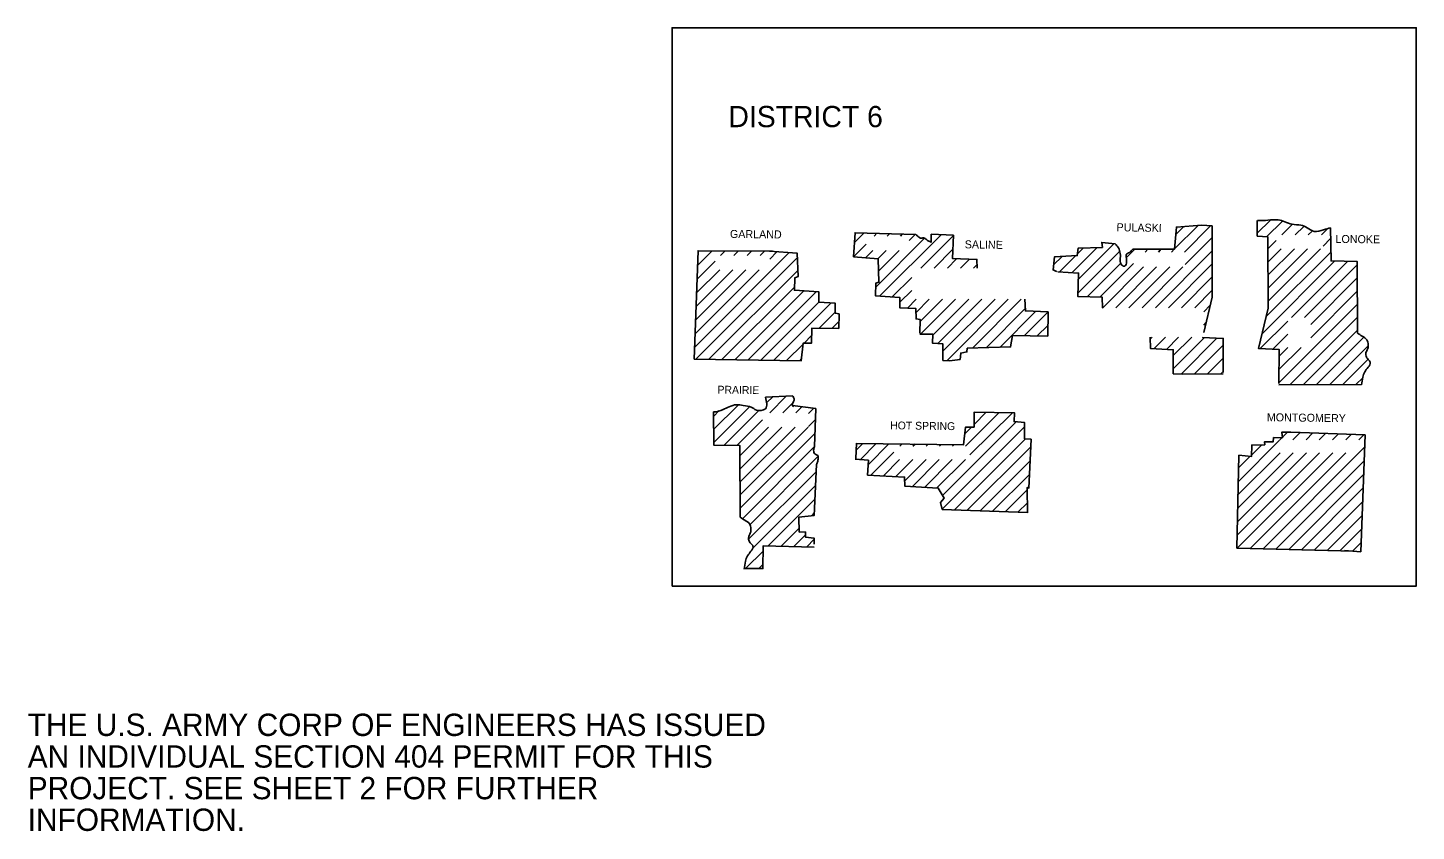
# Model space of a CAD drawing. Extents: x 21307 to 29830, y 1322443 to 1332359.
# Drawn here: x 27242 to 27988, y 1326076 to 1326507 of the extents above; entities that cross this region are included whole.
import ezdxf

# ---------------------------------------------------------------- set-up
doc = ezdxf.new("R2010")
doc.units = 0
doc.layers.add('R_Draft', color=7, linetype='Continuous')

msp = doc.modelspace()

# ---------------------------------------------------------------- linework, layer by layer
at = {"layer": 'R_Draft'}
for p, q in [((27727.22, 1326392.26), (27727.22, 1326396.66)), ((27693.42, 1326275.06), (27686.32, 1326275.76))]:
    msp.add_line(p, q, dxfattribs=at)
msp.add_lwpolyline([(27587.92, 1326207.46), (27587.92, 1326507.46), (27987.92, 1326507.46), (27987.92, 1326207.46)], close=True, dxfattribs=at)
for points in [[(27685.42, 1326384.46), (27686.32, 1326397.36), (27719.02, 1326396.36)], [(27835.52, 1326388.46), (27858.02, 1326388.56), (27859.02, 1326400.36), (27872.42, 1326401.36)], [(27858.02, 1326388.66), (27870.62, 1326401.26)], [(27858.72, 1326396.36), (27863.02, 1326400.66)], [(27863.42, 1326386.96), (27877.42, 1326400.96)], [(27872.42, 1326401.36), (27878.22, 1326400.96), (27878.32, 1326362.76), (27873.72, 1326343.66)], [(27902.42, 1326397.06), (27909.52, 1326404.06)], [(27902.42, 1326395.46), (27902.42, 1326403.86)], [(27907.52, 1326395.06), (27916.02, 1326403.56)], [(27915.72, 1326396.16), (27921.42, 1326401.86)], [(27922.82, 1326396.16), (27927.42, 1326400.76)], [(27929.92, 1326396.16), (27932.02, 1326398.26)], [(27936.92, 1326396.16), (27940.02, 1326399.26)], [(27941.92, 1326400.06), (27942.12, 1326382.16), (27956.22, 1326381.86), (27956.32, 1326343.46)], [(27685.42, 1326384.46), (27692.22, 1326391.26)], [(27685.92, 1326392.06), (27691.12, 1326397.26)], [(27696.52, 1326395.56), (27698.02, 1326397.06)], [(27697.42, 1326368.16), (27723.42, 1326394.26)], [(27699.62, 1326363.36), (27732.52, 1326396.26)], [(27703.62, 1326395.56), (27704.72, 1326396.76)], [(27710.72, 1326395.56), (27711.62, 1326396.56)], [(27715.32, 1326393.16), (27718.52, 1326396.36)], [(27721.72, 1326378.36), (27739.02, 1326395.66)], [(27727.22, 1326396.66), (27739.12, 1326395.96), (27738.72, 1326383.46), (27751.82, 1326382.96), (27751.92, 1326378.36)], [(27727.22, 1326392.26), (27727.22, 1326392.16)], [(27794.52, 1326376.36), (27794.52, 1326376.46), (27792.72, 1326377.36), (27793.42, 1326384.36), (27805.72, 1326385.06), (27806.12, 1326388.96), (27819.22, 1326389.46), (27818.92, 1326392.16), (27826.12, 1326391.36)], [(27806.32, 1326372.36), (27825.32, 1326391.36)], [(27863.72, 1326380.26), (27878.22, 1326394.76)], [(27914.12, 1326316.26), (27914.22, 1326334.66), (27903.12, 1326335.16), (27908.32, 1326356.86), (27908.22, 1326395.06), (27902.42, 1326395.46)], [(27908.22, 1326388.66), (27912.72, 1326393.16)], [(27937.92, 1326390.16), (27941.92, 1326394.16)], [(27599.72, 1326329.36), (27601.92, 1326387.66), (27641.92, 1326387.46)], [(27600.02, 1326335.76), (27650.92, 1326386.66)], [(27600.72, 1326329.36), (27655.22, 1326383.86)], [(27601.62, 1326379.76), (27609.42, 1326387.56)], [(27601.92, 1326387.06), (27602.42, 1326387.66)], [(27614.02, 1326385.06), (27616.52, 1326387.56)], [(27621.12, 1326385.06), (27623.52, 1326387.46)], [(27628.22, 1326385.06), (27630.62, 1326387.46)], [(27635.22, 1326385.06), (27637.62, 1326387.46)], [(27640.32, 1326387.46), (27655.22, 1326386.36), (27655.62, 1326373.76), (27653.92, 1326373.16), (27653.72, 1326366.46), (27666.82, 1326365.56), (27666.82, 1326360.06), (27675.52, 1326359.56), (27675.62, 1326354.06), (27677.72, 1326353.76), (27677.62, 1326345.86)], [(27640.42, 1326383.16), (27644.32, 1326387.06)], [(27721.12, 1326343.36), (27721.22, 1326350.76), (27719.12, 1326351.06), (27719.02, 1326356.56), (27710.32, 1326357.06), (27710.32, 1326362.56), (27697.22, 1326363.46), (27697.42, 1326370.16), (27699.12, 1326370.76), (27698.72, 1326383.36), (27685.42, 1326384.36)], [(27691.92, 1326383.86), (27695.92, 1326387.86)], [(27698.52, 1326383.36), (27703.02, 1326387.86)], [(27699.02, 1326376.86), (27710.02, 1326387.86)], [(27728.72, 1326378.36), (27738.82, 1326388.46)], [(27735.92, 1326378.36), (27740.82, 1326383.36)], [(27742.92, 1326378.36), (27747.72, 1326383.16)], [(27793.02, 1326380.16), (27797.52, 1326384.66)], [(27796.22, 1326376.36), (27805.02, 1326385.16)], [(27802.92, 1326375.96), (27816.22, 1326389.26)], [(27805.82, 1326385.96), (27808.92, 1326389.06)], [(27806.02, 1326364.96), (27828.52, 1326387.36)], [(27832.02, 1326383.86), (27836.62, 1326388.46)], [(27842.22, 1326386.96), (27843.72, 1326388.46)], [(27847.72, 1326357.06), (27878.22, 1326387.66)], [(27849.32, 1326386.96), (27850.72, 1326388.46)], [(27856.32, 1326386.96), (27857.82, 1326388.46)], [(27907.32, 1326352.36), (27942.12, 1326387.16)], [(27908.32, 1326360.56), (27936.42, 1326388.66)], [(27908.32, 1326367.56), (27929.42, 1326388.66)], [(27908.32, 1326374.66), (27922.42, 1326388.66)], [(27908.32, 1326381.66), (27915.32, 1326388.66)], [(27600.32, 1326343.06), (27634.72, 1326377.46)], [(27600.52, 1326350.36), (27627.62, 1326377.46)], [(27600.82, 1326357.76), (27620.62, 1326377.46)], [(27601.12, 1326365.06), (27613.52, 1326377.46)], [(27601.42, 1326372.46), (27611.02, 1326382.06)], [(27607.72, 1326329.36), (27655.52, 1326377.06)], [(27750.02, 1326378.36), (27751.82, 1326380.16)], [(27819.32, 1326357.06), (27819.12, 1326362.66), (27806.02, 1326363.16), (27806.42, 1326375.66), (27795.22, 1326376.36)], [(27811.12, 1326362.96), (27829.22, 1326381.06)], [(27817.92, 1326362.66), (27836.02, 1326380.76)], [(27819.32, 1326356.96), (27819.42, 1326357.06), (27841.32, 1326378.96)], [(27826.42, 1326357.06), (27848.32, 1326378.96)], [(27833.52, 1326357.06), (27855.42, 1326378.96)], [(27840.62, 1326357.06), (27862.52, 1326378.96)], [(27854.72, 1326357.06), (27878.22, 1326380.56)], [(27905.02, 1326343.06), (27944.02, 1326382.06)], [(27920.92, 1326351.86), (27950.92, 1326381.86)], [(27927.92, 1326351.86), (27956.22, 1326380.16)], [(27614.72, 1326329.16), (27653.72, 1326368.16)], [(27706.22, 1326362.86), (27716.72, 1326373.36)], [(27861.82, 1326357.06), (27878.22, 1326373.56)], [(27931.22, 1326348.06), (27956.22, 1326373.06)], [(27621.72, 1326329.06), (27658.72, 1326366.16)], [(27628.62, 1326328.96), (27665.32, 1326365.66)], [(27635.62, 1326328.86), (27666.82, 1326360.06)], [(27710.32, 1326359.96), (27716.72, 1326366.36)], [(27714.42, 1326356.86), (27719.12, 1326361.56)], [(27719.12, 1326354.56), (27726.12, 1326361.56)], [(27721.22, 1326349.56), (27733.22, 1326361.56)], [(27721.52, 1326342.76), (27740.32, 1326361.56)], [(27728.12, 1326342.36), (27747.42, 1326361.56)], [(27730.72, 1326337.86), (27754.42, 1326361.56)], [(27733.52, 1326333.66), (27761.52, 1326361.56)], [(27735.62, 1326328.56), (27768.62, 1326361.56)], [(27749.42, 1326335.36), (27775.62, 1326361.56)], [(27777.52, 1326361.56), (27777.82, 1326355.36), (27790.02, 1326354.76), (27789.92, 1326341.76)], [(27868.92, 1326357.06), (27878.22, 1326366.46)], [(27931.22, 1326340.96), (27956.22, 1326365.96)], [(27642.62, 1326328.86), (27673.42, 1326359.66)], [(27666.82, 1326345.96), (27675.52, 1326354.66)], [(27756.72, 1326335.56), (27777.72, 1326356.56)], [(27764.02, 1326335.76), (27783.22, 1326355.06)], [(27777.22, 1326341.86), (27790.02, 1326354.76)], [(27873.72, 1326354.86), (27877.22, 1326358.36)], [(27914.22, 1326316.86), (27956.22, 1326358.86)], [(27677.62, 1326345.86), (27663.02, 1326346.06), (27662.92, 1326338.06), (27658.42, 1326338.06), (27657.32, 1326328.56), (27599.72, 1326329.36)], [(27673.82, 1326345.86), (27677.62, 1326349.66)], [(27784.22, 1326341.86), (27789.92, 1326347.56)], [(27873.72, 1326347.76), (27875.02, 1326349.06)], [(27904.22, 1326335.26), (27918.82, 1326349.86)], [(27920.02, 1326315.66), (27956.22, 1326351.86)], [(27658.92, 1326338.06), (27662.92, 1326342.06)], [(27737.12, 1326328.46), (27733.52, 1326328.76), (27733.52, 1326337.56), (27727.92, 1326337.96), (27728.12, 1326342.76), (27721.12, 1326342.86)], [(27789.92, 1326341.76), (27770.82, 1326342.06), (27769.92, 1326335.96), (27746.62, 1326335.26), (27746.42, 1326333.26), (27743.12, 1326332.66), (27742.72, 1326329.26), (27737.12, 1326328.46)], [(27857.22, 1326321.46), (27857.32, 1326334.46), (27845.12, 1326335.06), (27844.82, 1326341.26)], [(27844.92, 1326340.16), (27846.02, 1326341.26)], [(27846.82, 1326334.96), (27853.12, 1326341.26)], [(27853.62, 1326334.66), (27860.22, 1326341.26)], [(27857.22, 1326324.26), (27874.02, 1326340.96)], [(27857.32, 1326331.36), (27867.22, 1326341.26)], [(27861.52, 1326321.36), (27880.82, 1326340.76)], [(27873.22, 1326341.26), (27873.12, 1326341.06), (27884.22, 1326340.56), (27884.12, 1326322.16)], [(27911.02, 1326334.96), (27918.82, 1326342.76)], [(27927.12, 1326315.66), (27956.22, 1326344.76)], [(27934.22, 1326315.66), (27959.62, 1326341.06)], [(27649.52, 1326328.66), (27658.32, 1326337.46)], [(27868.62, 1326321.36), (27884.12, 1326336.96)], [(27914.22, 1326323.96), (27926.02, 1326335.76)], [(27914.22, 1326331.06), (27918.92, 1326335.76)], [(27941.32, 1326315.66), (27961.92, 1326336.36)], [(27656.52, 1326328.56), (27657.42, 1326329.56)], [(27875.72, 1326321.46), (27884.12, 1326329.86)], [(27882.82, 1326321.46), (27884.12, 1326322.86)], [(27948.42, 1326315.76), (27962.12, 1326329.46)], [(27862.02, 1326321.36), (27857.22, 1326321.46)], [(27884.12, 1326321.56), (27862.02, 1326321.36)], [(27958.52, 1326315.76), (27914.12, 1326315.56)], [(27955.52, 1326315.76), (27959.22, 1326319.46)], [(27638.12, 1326308.96), (27652.62, 1326309.66)], [(27639.12, 1326306.36), (27641.82, 1326309.06)], [(27640.42, 1326300.56), (27649.32, 1326309.46)], [(27610.12, 1326298.56), (27613.32, 1326301.76)], [(27624.52, 1326244.56), (27624.42, 1326282.96), (27610.32, 1326283.26), (27610.12, 1326301.16)], [(27610.22, 1326291.56), (27623.42, 1326304.76)], [(27610.32, 1326284.66), (27629.52, 1326303.86)], [(27615.92, 1326283.16), (27634.52, 1326301.76)], [(27647.42, 1326300.56), (27653.12, 1326306.26)], [(27652.62, 1326304.46), (27665.12, 1326302.86), (27664.42, 1326282.46)], [(27654.52, 1326300.56), (27657.72, 1326303.76)], [(27661.22, 1326300.26), (27664.02, 1326302.96)], [(27687.02, 1326284.06), (27744.62, 1326283.46), (27745.72, 1326292.96), (27750.22, 1326292.96), (27750.32, 1326300.96), (27771.92, 1326300.66), (27771.72, 1326295.86), (27777.32, 1326295.46), (27777.32, 1326286.66), (27780.92, 1326286.36), (27779.72, 1326260.16), (27778.82, 1326260.46), (27778.92, 1326246.86)], [(27745.72, 1326282.66), (27763.82, 1326300.76)], [(27748.02, 1326277.96), (27770.82, 1326300.66)], [(27750.22, 1326294.26), (27756.82, 1326300.86)], [(27622.72, 1326282.96), (27636.62, 1326296.86)], [(27624.42, 1326277.56), (27639.82, 1326292.96)], [(27624.52, 1326256.46), (27661.02, 1326292.96)], [(27624.52, 1326263.56), (27654.02, 1326292.96)], [(27624.52, 1326270.56), (27646.92, 1326292.96)], [(27661.22, 1326293.16), (27664.92, 1326296.86)], [(27733.12, 1326248.86), (27777.32, 1326293.06)], [(27733.32, 1326256.16), (27772.82, 1326295.66)], [(27745.32, 1326289.26), (27748.92, 1326292.96)], [(27624.52, 1326249.36), (27664.62, 1326289.46)], [(27739.82, 1326248.46), (27777.92, 1326286.66)], [(27891.5, 1326227.87), (27892.6, 1326277.77), (27899.4, 1326277.17), (27899.5, 1326283.27), (27906.5, 1326283.47), (27906.4, 1326285.07), (27911.1, 1326285.07), (27911.2, 1326287.27), (27916, 1326287.17), (27915.6, 1326290.17), (27920.6, 1326290.27)], [(27892.3, 1326263.77), (27914.4, 1326285.87)], [(27914.6, 1326286.07), (27915.7, 1326287.17)], [(27915.9, 1326287.37), (27918.7, 1326290.17)], [(27920.6, 1326290.27), (27960.4, 1326288.77)], [(27921.6, 1326286.07), (27925.6, 1326290.07)], [(27928.7, 1326286.07), (27932.4, 1326289.77)], [(27935.8, 1326286.07), (27939.3, 1326289.57)], [(27942.9, 1326286.07), (27946.1, 1326289.27)], [(27950, 1326286.07), (27952.9, 1326288.97)], [(27957, 1326286.07), (27959.7, 1326288.77)], [(27960.4, 1326288.77), (27958.1, 1326225.97)], [(27626.02, 1326243.76), (27664.02, 1326281.86)], [(27686.72, 1326275.96), (27687.02, 1326284.26)], [(27686.92, 1326280.46), (27690.52, 1326284.06)], [(27689.12, 1326275.56), (27697.52, 1326283.96)], [(27693.42, 1326272.76), (27704.52, 1326283.96)], [(27694.82, 1326267.06), (27707.12, 1326279.46)], [(27710.42, 1326282.66), (27711.52, 1326283.86)], [(27717.42, 1326282.66), (27718.52, 1326283.76)], [(27724.52, 1326282.66), (27725.42, 1326283.56)], [(27731.62, 1326282.66), (27732.42, 1326283.46)], [(27738.72, 1326282.66), (27739.42, 1326283.46)], [(27746.62, 1326248.26), (27780.72, 1326282.26)], [(27891.6, 1326227.77), (27891.7, 1326227.87), (27943.1, 1326279.17)], [(27891.7, 1326234.87), (27936, 1326279.17)], [(27891.8, 1326242.07), (27928.9, 1326279.17)], [(27892, 1326249.37), (27921.8, 1326279.17)], [(27892.1, 1326256.57), (27914.7, 1326279.17)], [(27898.6, 1326227.67), (27950.1, 1326279.17)], [(27899.5, 1326278.07), (27904.9, 1326283.37)], [(27905.6, 1326227.57), (27960.2, 1326282.17)], [(27906.4, 1326284.97), (27906.6, 1326285.07)], [(27629.92, 1326240.56), (27666.32, 1326277.06)], [(27665.52, 1326272.86), (27664.32, 1326245.46), (27656.12, 1326244.56), (27656.32, 1326236.46), (27659.62, 1326236.56), (27659.72, 1326233.76), (27664.22, 1326233.26), (27664.32, 1326229.96)], [(27778.92, 1326247.06), (27733.12, 1326248.66), (27732.22, 1326252.36), (27734.12, 1326254.76), (27731.02, 1326260.16), (27713.02, 1326261.26), (27712.92, 1326266.06), (27693.02, 1326267.16), (27693.42, 1326275.06)], [(27701.52, 1326266.76), (27710.22, 1326275.46)], [(27708.22, 1326266.36), (27717.32, 1326275.46)], [(27713.02, 1326264.06), (27724.42, 1326275.46)], [(27717.12, 1326261.06), (27731.52, 1326275.46)], [(27723.72, 1326260.66), (27738.52, 1326275.46)], [(27730.32, 1326260.26), (27745.62, 1326275.46)], [(27753.52, 1326247.96), (27780.32, 1326274.86)], [(27892.4, 1326270.97), (27898.7, 1326277.27)], [(27912.4, 1326227.37), (27959.9, 1326274.77)], [(27629.02, 1326232.66), (27665.32, 1326268.96)], [(27760.22, 1326247.66), (27780.02, 1326267.46)], [(27919.4, 1326227.17), (27959.6, 1326267.47)], [(27631.52, 1326228.06), (27665.02, 1326261.56)], [(27767.02, 1326247.46), (27778.82, 1326259.16)], [(27926.2, 1326226.97), (27959.3, 1326260.07)], [(27639.62, 1326229.16), (27664.72, 1326254.16)], [(27773.82, 1326247.16), (27778.92, 1326252.16)], [(27933.1, 1326226.87), (27959.1, 1326252.77)], [(27662.82, 1326245.26), (27664.32, 1326246.76)], [(27940.1, 1326226.67), (27958.8, 1326245.47)], [(27646.52, 1326228.96), (27656.32, 1326238.66)], [(27653.42, 1326228.76), (27659.72, 1326235.06)], [(27946.9, 1326226.47), (27958.5, 1326238.07)], [(27664.32, 1326228.46), (27636.92, 1326229.16), (27636.72, 1326216.86), (27626.72, 1326216.86)], [(27627.42, 1326216.96), (27637.02, 1326226.46)], [(27660.32, 1326228.56), (27664.32, 1326232.66)], [(27954.4, 1326226.27), (27891.7, 1326227.87)], [(27949.4, 1326226.37), (27949.4, 1326226.57), (27958.1, 1326225.97)], [(27953.9, 1326226.37), (27958.2, 1326230.77)], [(27634.52, 1326216.96), (27636.72, 1326219.16)]]:
    msp.add_lwpolyline(points, dxfattribs=at)
for points in [[(27902.62, 1326403.86), (27908.22, 1326404.06), (27913.72, 1326404.26), (27917.22, 1326403.26), (27921.22, 1326401.96), (27925.92, 1326401.36), (27929.22, 1326400.06), (27933.12, 1326398.06), (27938.12, 1326398.96), (27941.92, 1326399.96)], [(27719.02, 1326396.36), (27720.22, 1326395.26), (27721.52, 1326394.46), (27723.12, 1326394.56), (27724.62, 1326393.66), (27727.22, 1326392.26)], [(27826.12, 1326391.36), (27827.82, 1326389.16), (27828.82, 1326386.16), (27828.82, 1326382.76), (27829.62, 1326379.96), (27831.22, 1326379.36), (27832.22, 1326381.76), (27832.02, 1326384.16), (27832.02, 1326385.56), (27833.72, 1326386.76), (27835.52, 1326388.46)], [(27956.32, 1326343.46), (27958.82, 1326341.76), (27961.42, 1326339.76), (27962.12, 1326337.06), (27961.92, 1326335.16), (27961.12, 1326333.56), (27960.92, 1326331.06), (27962.12, 1326329.26), (27963.22, 1326327.76), (27962.12, 1326325.06), (27960.22, 1326322.56), (27959.22, 1326319.76), (27958.52, 1326315.56)], [(27610.12, 1326301.06), (27610.22, 1326301.06), (27615.32, 1326302.36), (27618.62, 1326303.76), (27622.42, 1326304.96), (27626.22, 1326304.46), (27630.52, 1326303.66), (27633.22, 1326302.06), (27638.12, 1326302.76), (27638.12, 1326308.96)], [(27652.72, 1326309.66), (27653.52, 1326308.06), (27653.22, 1326306.66), (27652.62, 1326304.46), (27653.12, 1326303.76)], [(27664.42, 1326282.46), (27664.02, 1326280.46), (27664.82, 1326278.36), (27666.22, 1326277.66), (27666.42, 1326275.66), (27665.92, 1326273.66), (27665.52, 1326272.86)], [(27626.72, 1326216.66), (27627.42, 1326220.86), (27628.42, 1326223.66), (27630.32, 1326226.16), (27631.42, 1326228.86), (27630.32, 1326230.36), (27629.12, 1326232.16), (27629.32, 1326234.66), (27630.12, 1326236.26), (27630.32, 1326238.16), (27629.62, 1326240.86), (27627.02, 1326242.86), (27624.52, 1326244.56)]]:
    msp.add_spline(points, degree=3, dxfattribs=at)

# ---------------------------------------------------------------- texts
for s, height, p in [('DISTRICT 6', 11.4, (27618.22, 1326454.06)), ('THE U.S. ARMY CORP OF ENGINEERS HAS ISSUED', 12, (27241.58, 1326126.95)), ('AN INDIVIDUAL SECTION 404 PERMIT FOR THIS', 12, (27241.58, 1326109.95)), ('PROJECT. SEE SHEET 2 FOR FURTHER', 12, (27241.58, 1326092.95)), ('INFORMATION.', 12, (27241.58, 1326075.95))]:
    msp.add_text(s, height=height, dxfattribs=at).set_placement(p)
for s, height, rotation, p in [('GARLAND', 4.301, 359.36576, (27619.02, 1326394.56)), ('PULASKI', 4.301, 359.05305, (27826.82, 1326398.16)), ('SALINE', 4.301, 359.14914, (27745.22, 1326388.96)), ('LONOKE', 4.301, 359.49742, (27944.52, 1326391.86)), ('PRAIRIE', 4.201, 359.21158, (27612.32, 1326310.96)), ('MONTGOMERY', 4.301, 359.29442, (27907.6, 1326296.07)), ('HOT SPRING', 4.201, 359.22157, (27705.12, 1326291.76))]:
    msp.add_text(s, height=height, rotation=rotation, dxfattribs=at).set_placement(p)

doc.saveas('drawing.dxf')
